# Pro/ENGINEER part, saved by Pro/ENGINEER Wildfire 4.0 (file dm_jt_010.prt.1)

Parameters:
  METRIC = "NO"

Other parameters: PITCH, DRILL_POINT_ANGLE, DRILL_DEPTH, DRILL_DIAMETER, THREAD_DIAMETER, THREADS_PER_INCH, THREAD_DEPTH, THREAD_LENGTH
